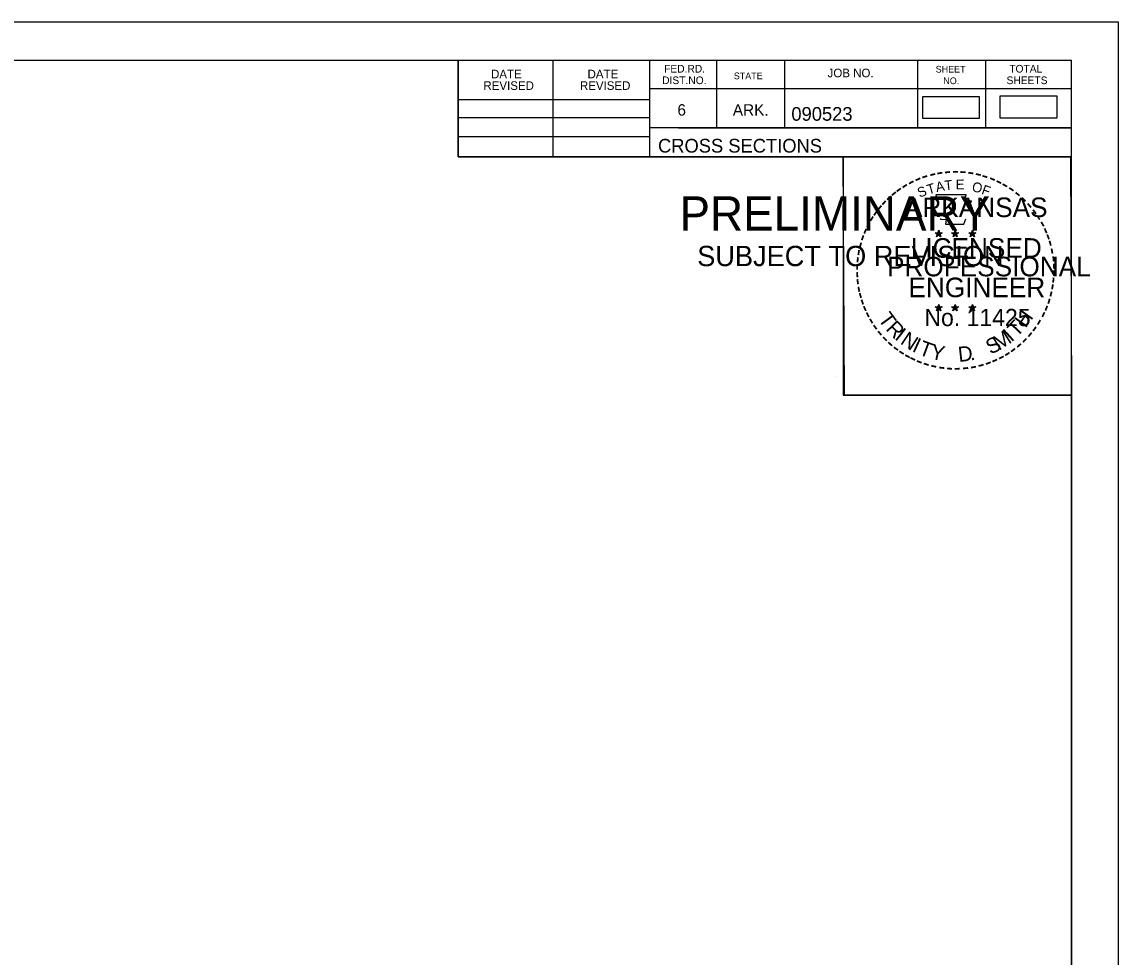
# Model space of a CAD drawing. Extents: x 1406028 to 1412453, y 321733 to 325986.
# Drawn here: x 1406640.9 to 1406752.8, y 324610.6 to 324706.1 of the extents above; entities that cross this region are included whole.
import ezdxf

# ---------------------------------------------------------------- set-up
doc = ezdxf.new("R2010")
doc.units = 0
for name, color, linetype in [('R_Border', 7, 'Continuous'), ('R_Border PE', 7, 'Continuous'), ('R_Border Prem', 7, 'Continuous'), ('R_Fin Surface', 7, 'Continuous'), ('R_No Plot', 7, 'Continuous')]:
    doc.layers.add(name, color=color, linetype=linetype)

msp = doc.modelspace()

# ---------------------------------------------------------------- linework, layer by layer
at = {"layer": 'R_Border'}
for p, q in [((1406431.89, 324702.17), (1406748.07, 324702.17)), ((1406685.43, 324692.29), (1406685.43, 324702.17)), ((1406695.11, 324692.29), (1406695.11, 324702.17)), ((1406704.97, 324702.17), (1406704.97, 324692.29)), ((1406711.81, 324702.17), (1406711.81, 324695.23)), ((1406718.75, 324702.17), (1406718.75, 324695.23)), ((1406732.33, 324702.17), (1406732.33, 324695.23)), ((1406739.27, 324702.17), (1406739.27, 324695.23)), ((1406748.07, 324496.71), (1406748.07, 324702.17)), ((1406748.07, 324699.23), (1406704.97, 324699.23)), ((1406748.07, 324699.25), (1406748.07, 324699.25)), ((1406685.43, 324698.15), (1406704.97, 324698.15)), ((1406685.43, 324696.29), (1406704.97, 324696.29)), ((1406748.07, 324695.23), (1406704.97, 324695.23)), ((1406707.93, 324695.23), (1406748.07, 324695.23)), ((1406685.43, 324694.35), (1406704.97, 324694.35)), ((1406748.07, 324692.29), (1406685.43, 324692.29))]:
    msp.add_line(p, q, dxfattribs=at)
at = {"layer": 'R_Border PE'}
for p, q in [((1406734.15, 324684.54), (1406734.5, 324684.43)), ((1406734.15, 324684.54), (1406734.41, 324684.5)), ((1406734.15, 324684.54), (1406734.39, 324684.42)), ((1406734.29, 324684.13), (1406734.5, 324684.43)), ((1406734.29, 324684.13), (1406734.41, 324684.38)), ((1406734.29, 324684.13), (1406734.5, 324684.35)), ((1406734.5, 324684.8), (1406734.46, 324684.54)), ((1406734.5, 324684.43), (1406734.5, 324684.8)), ((1406734.5, 324684.8), (1406734.55, 324684.55)), ((1406734.85, 324684.54), (1406734.5, 324684.43)), ((1406734.72, 324684.13), (1406734.5, 324684.43)), ((1406734.72, 324684.13), (1406734.5, 324684.35)), ((1406734.85, 324684.54), (1406734.56, 324684.49)), ((1406734.72, 324684.13), (1406734.58, 324684.43)), ((1406734.85, 324684.54), (1406734.65, 324684.44)), ((1406735.82, 324684.54), (1406736.17, 324684.43)), ((1406735.82, 324684.54), (1406736.08, 324684.5)), ((1406735.82, 324684.54), (1406736.06, 324684.42)), ((1406735.96, 324684.13), (1406736.17, 324684.43)), ((1406735.96, 324684.13), (1406736.08, 324684.38)), ((1406735.96, 324684.13), (1406736.17, 324684.35)), ((1406736.17, 324684.8), (1406736.13, 324684.54)), ((1406736.17, 324684.43), (1406736.17, 324684.8)), ((1406736.17, 324684.8), (1406736.22, 324684.55)), ((1406736.52, 324684.54), (1406736.17, 324684.43)), ((1406736.39, 324684.13), (1406736.17, 324684.43)), ((1406736.39, 324684.13), (1406736.17, 324684.35)), ((1406736.52, 324684.54), (1406736.23, 324684.49)), ((1406736.39, 324684.13), (1406736.25, 324684.43)), ((1406736.52, 324684.54), (1406736.32, 324684.44)), ((1406737.59, 324684.53), (1406737.94, 324684.42)), ((1406737.59, 324684.53), (1406737.84, 324684.49)), ((1406737.59, 324684.53), (1406737.83, 324684.41)), ((1406737.72, 324684.12), (1406737.94, 324684.42)), ((1406737.72, 324684.12), (1406737.85, 324684.37)), ((1406737.72, 324684.12), (1406737.94, 324684.34)), ((1406737.94, 324684.78), (1406737.9, 324684.53)), ((1406737.94, 324684.42), (1406737.94, 324684.78)), ((1406737.94, 324684.78), (1406737.99, 324684.53)), ((1406738.28, 324684.53), (1406737.94, 324684.42)), ((1406738.15, 324684.12), (1406737.94, 324684.42)), ((1406738.15, 324684.12), (1406737.94, 324684.34)), ((1406738.28, 324684.53), (1406738, 324684.48)), ((1406738.15, 324684.12), (1406738.01, 324684.41)), ((1406738.28, 324684.53), (1406738.08, 324684.43)), ((1406734.15, 324676.97), (1406734.5, 324676.86)), ((1406734.15, 324676.97), (1406734.4, 324676.92)), ((1406734.15, 324676.97), (1406734.39, 324676.85)), ((1406734.28, 324676.56), (1406734.5, 324676.86)), ((1406734.28, 324676.56), (1406734.41, 324676.81)), ((1406734.28, 324676.56), (1406734.5, 324676.78)), ((1406734.5, 324677.22), (1406734.46, 324676.97)), ((1406734.5, 324676.86), (1406734.5, 324677.22)), ((1406734.5, 324677.22), (1406734.55, 324676.97)), ((1406734.85, 324676.97), (1406734.5, 324676.86)), ((1406734.71, 324676.56), (1406734.5, 324676.86)), ((1406734.71, 324676.56), (1406734.5, 324676.78)), ((1406734.85, 324676.97), (1406734.56, 324676.92)), ((1406734.71, 324676.56), (1406734.58, 324676.85)), ((1406734.85, 324676.97), (1406734.64, 324676.87)), ((1406735.82, 324676.97), (1406736.17, 324676.86)), ((1406735.82, 324676.97), (1406736.07, 324676.92)), ((1406735.82, 324676.97), (1406736.06, 324676.85)), ((1406735.95, 324676.56), (1406736.17, 324676.86)), ((1406735.95, 324676.56), (1406736.08, 324676.81)), ((1406735.95, 324676.56), (1406736.17, 324676.78)), ((1406736.17, 324677.22), (1406736.13, 324676.97)), ((1406736.17, 324676.86), (1406736.17, 324677.22)), ((1406736.17, 324677.22), (1406736.22, 324676.97)), ((1406736.52, 324676.97), (1406736.17, 324676.86)), ((1406736.38, 324676.56), (1406736.17, 324676.86)), ((1406736.38, 324676.56), (1406736.17, 324676.78)), ((1406736.52, 324676.97), (1406736.23, 324676.92)), ((1406736.38, 324676.56), (1406736.24, 324676.85)), ((1406736.52, 324676.97), (1406736.31, 324676.87)), ((1406737.59, 324676.96), (1406737.94, 324676.85)), ((1406737.59, 324676.96), (1406737.84, 324676.91)), ((1406737.59, 324676.96), (1406737.82, 324676.84)), ((1406737.72, 324676.55), (1406737.94, 324676.85)), ((1406737.72, 324676.55), (1406737.85, 324676.8)), ((1406737.72, 324676.55), (1406737.93, 324676.77)), ((1406737.94, 324677.21), (1406737.89, 324676.96)), ((1406738.15, 324676.55), (1406737.93, 324676.77)), ((1406737.94, 324676.85), (1406737.94, 324677.21)), ((1406737.94, 324677.21), (1406737.98, 324676.96)), ((1406738.28, 324676.96), (1406737.94, 324676.85)), ((1406738.15, 324676.55), (1406737.94, 324676.85)), ((1406738.28, 324676.96), (1406738, 324676.91)), ((1406738.15, 324676.55), (1406738.01, 324676.84)), ((1406738.28, 324676.96), (1406738.08, 324676.86))]:
    msp.add_line(p, q, dxfattribs=at)
for points in [[(1406734.2, 324688.42), (1406734.46, 324687.59)], [(1406737.71, 324687.5), (1406737.85, 324687.78), (1406737.16, 324687.76), (1406737.31, 324688.42), (1406734.2, 324688.42)], [(1406734.69, 324686), (1406734.69, 324685.91), (1406735.25, 324685.89), (1406735.2, 324685.42), (1406737.07, 324685.42), (1406737.27, 324685.95)], [(1406734.5, 324684.8), (1406734.72, 324684.13), (1406734.15, 324684.54), (1406734.85, 324684.54), (1406734.29, 324684.13), (1406734.5, 324684.8)], [(1406736.17, 324684.8), (1406736.39, 324684.13), (1406735.82, 324684.54), (1406736.52, 324684.54), (1406735.96, 324684.13), (1406736.17, 324684.8)], [(1406737.94, 324684.78), (1406738.15, 324684.12), (1406737.59, 324684.53), (1406738.28, 324684.53), (1406737.72, 324684.12), (1406737.94, 324684.78)], [(1406734.5, 324677.22), (1406734.71, 324676.56), (1406734.15, 324676.97), (1406734.85, 324676.97), (1406734.28, 324676.56), (1406734.5, 324677.22)], [(1406736.17, 324677.22), (1406736.38, 324676.56), (1406735.82, 324676.97), (1406736.52, 324676.97), (1406735.95, 324676.56), (1406736.17, 324677.22)], [(1406737.94, 324677.21), (1406738.15, 324676.55), (1406737.59, 324676.96), (1406738.28, 324676.96), (1406737.72, 324676.55), (1406737.94, 324677.21)]]:
    msp.add_lwpolyline(points, dxfattribs=at)
for centre, radius in [((1406734.5, 324684.43), 0.172), ((1406734.5, 324684.43), 0.145), ((1406734.5, 324684.43), 0.116), ((1406734.5, 324684.43), 0.0991), ((1406734.5, 324684.43), 0.0747), ((1406734.5, 324684.43), 0.0495), ((1406734.5, 324684.43), 0.0296), ((1406736.17, 324684.43), 0.172), ((1406736.17, 324684.43), 0.145), ((1406736.17, 324684.43), 0.116), ((1406736.17, 324684.43), 0.0991), ((1406736.17, 324684.43), 0.0747), ((1406736.17, 324684.43), 0.0495), ((1406736.17, 324684.43), 0.0296), ((1406737.94, 324684.42), 0.172), ((1406737.94, 324684.42), 0.145), ((1406737.94, 324684.42), 0.116), ((1406737.94, 324684.42), 0.0991), ((1406737.94, 324684.42), 0.0747), ((1406737.94, 324684.42), 0.0495), ((1406737.94, 324684.42), 0.0296), ((1406734.5, 324676.86), 0.172), ((1406734.5, 324676.86), 0.145), ((1406734.5, 324676.86), 0.116), ((1406734.5, 324676.86), 0.0991), ((1406734.5, 324676.86), 0.0747), ((1406734.5, 324676.86), 0.0495), ((1406734.5, 324676.86), 0.0296), ((1406736.17, 324676.86), 0.172), ((1406736.17, 324676.86), 0.145), ((1406736.17, 324676.86), 0.116), ((1406736.17, 324676.86), 0.0991), ((1406736.17, 324676.86), 0.0747), ((1406736.17, 324676.86), 0.0495), ((1406736.17, 324676.86), 0.0296), ((1406737.93, 324676.85), 0.172), ((1406737.93, 324676.85), 0.145), ((1406737.93, 324676.85), 0.116), ((1406737.93, 324676.85), 0.0991), ((1406737.93, 324676.85), 0.0747), ((1406737.93, 324676.85), 0.0495), ((1406737.93, 324676.85), 0.0296)]:
    msp.add_circle(centre, radius, dxfattribs=at)
at = {"layer": 'R_Fin Surface'}
for points in [[(1406732.85, 324696.23), (1406738.68, 324696.23), (1406738.68, 324698.42), (1406732.85, 324698.42)], [(1406740.76, 324696.28), (1406746.59, 324696.28), (1406746.59, 324698.47), (1406740.76, 324698.47)]]:
    msp.add_lwpolyline(points, close=True, dxfattribs=at)
at = {"layer": 'R_No Plot'}
for p, q in [((1406419.49, 324706.06), (1406752.82, 324706.06)), ((1406724.1, 324669.83), (1406724.1, 324669.83))]:
    msp.add_line(p, q, dxfattribs=at)
for points in [[(1406419.48, 324706.06), (1406752.82, 324706.06), (1406752.82, 324492.72), (1406419.48, 324492.72)], [(1406665.81, 324702.17), (1406685.43, 324702.17), (1406685.43, 324692.29), (1406701.54, 324692.29), (1406724.74, 324692.29), (1406724.74, 324667.95), (1406748.07, 324667.95), (1406748.07, 324496.71), (1406431.89, 324496.71), (1406431.89, 324702.17)], [(1406724.74, 324692.29), (1406747.95, 324692.29), (1406748.07, 324667.95), (1406724.86, 324667.95)]]:
    msp.add_lwpolyline(points, close=True, dxfattribs=at)

# ---------------------------------------------------------------- texts
at = {"layer": 'R_Border'}
for s, height, p in [('DATE', 0.879, (1406688.77, 324700.3)), ('DATE', 0.879, (1406698.63, 324700.3)), ('FED.RD.', 0.782, (1406706.45, 324700.89)), ('STATE', 0.684, (1406713.57, 324700.21)), ('JOB NO.', 0.879, (1406723.15, 324700.41)), ('SHEET', 0.684, (1406734.19, 324700.89)), ('TOTAL', 0.782, (1406741.71, 324700.89)), ('REVISED', 0.879, (1406687.99, 324699.12)), ('REVISED', 0.879, (1406697.85, 324699.12)), ('DIST.NO.', 0.782, (1406706.25, 324699.71)), ('NO.', 0.684, (1406734.97, 324699.71)), ('SHEETS', 0.782, (1406741.43, 324699.71)), ('6', 1.17, (1406707.81, 324696.49)), ('ARK.', 1.172, (1406713.47, 324696.49)), ('090523', 1.4, (1406719.45, 324695.97)), ('CROSS SECTIONS', 1.4, (1406705.83, 324692.72))]:
    msp.add_text(s, height=height, rotation=360, dxfattribs=at).set_placement(p)
at = {"layer": 'R_Border PE'}
for s, height, rotation, p in [('-', 1.6, 10.2193, (1406734.37, 324689.95)), ('-', 1.6, 5.8968, (1406735.1, 324690.06)), ('-', 1.6, 0.1862, (1406735.87, 324690.13)), ('-', 1.6, 357.743, (1406736.6, 324690.12)), ('-', 1.6, 352.1617, (1406737.34, 324690.06)), ('-', 1.6, 28.7918, (1406731.68, 324688.96)), ('-', 1.6, 24.3072, (1406732.31, 324689.28)), ('-', 1.6, 19.1761, (1406732.94, 324689.55)), ('T', 1, 16.4036, (1406733.46, 324688.43)), ('-', 1.6, 13.6301, (1406733.69, 324689.79)), ('A', 1, 11.2132, (1406734.29, 324688.68)), ('T', 1, 6.0228, (1406735.14, 324688.85)), ('E', 1, 0.8323, (1406736.24, 324688.96)), ('O', 1, 350.4515, (1406737.85, 324688.75)), ('-', 1.6, 347.2049, (1406738.06, 324689.95)), ('-', 1.6, 342.3362, (1406738.69, 324689.79)), ('-', 1.6, 337.8551, (1406739.43, 324689.57)), ('-', 1.6, 334.1211, (1406740.06, 324689.3)), ('-', 1.6, 38.9507, (1406730.03, 324687.82)), ('-', 1.6, 36.2317, (1406730.5, 324688.2)), ('-', 1.6, 34.0636, (1406731.08, 324688.59)), ('S', 1, 21.594, (1406732.55, 324688.1)), ('F', 1, 340.0707, (1406738.8, 324688.52)), ('-', 1.6, 329.6409, (1406740.64, 324689.02)), ('-', 1.6, 325.8627, (1406741.28, 324688.66)), ('-', 1.6, 320.5297, (1406741.89, 324688.23)), ('-', 1.6, 50.6142, (1406728.74, 324686.44)), ('-', 1.6, 48.423, (1406729.14, 324686.92)), ('-', 1.6, 42.9622, (1406729.59, 324687.4)), ('ARKANSAS', 2, 360, (1406731.05, 324686.13)), ('-', 1.6, 315.5786, (1406742.49, 324687.74)), ('-', 1.6, 309.8797, (1406743.06, 324687.19)), ('-', 1.6, 58.0706, (1406728, 324685.34)), ('-', 1.6, 54.2325, (1406728.33, 324685.87)), ('-', 1.6, 306.6522, (1406743.58, 324686.59)), ('-', 1.4, 303.6753, (1406744.07, 324686.02)), ('-', 1.6, 62.8713, (1406727.69, 324684.73)), ('-', 1.6, 299.6684, (1406744.39, 324685.42)), ('-', 1.6, 72.3945, (1406727.21, 324683.49)), ('-', 1.6, 67.7743, (1406727.43, 324684.12)), ('LICENSED', 2, 360, (1406731.65, 324681.98)), ('DWB', 0.01, 360, (1406734.49, 324684.43)), ('DWB', 0.01, 360, (1406736.16, 324684.43)), ('DWB', 0.01, 360, (1406737.92, 324684.42)), ('-', 1.6, 294.6628, (1406744.71, 324684.8)), ('-', 1.6, 290.5728, (1406744.97, 324684.23)), ('-', 1.6, 75.461, (1406727.02, 324682.77)), ('-', 1.6, 285.1233, (1406745.2, 324683.65)), ('-', 1.6, 280.5493, (1406745.4, 324682.9)), ('-', 1.6, 85.1863, (1406726.81, 324681.37)), ('-', 1.6, 81.2013, (1406726.88, 324682.06)), ('PROFESSIONAL', 2, 360, (1406729.22, 324680.08)), ('-', 1.6, 276.5962, (1406745.57, 324682.14)), ('-', 1.6, 89.0622, (1406726.78, 324680.67)), ('-', 1.6, 274.3301, (1406745.63, 324681.41)), ('-', 1.6, 269.9407, (1406745.66, 324680.78)), ('-', 1.6, 94.1959, (1406726.82, 324679.94)), ('-', 1.6, 98.9479, (1406726.89, 324679.28)), ('ENGINEER', 2, 360, (1406731.41, 324677.95)), ('-', 1.6, 263.5172, (1406745.64, 324680.12)), ('-', 1.6, 101.7149, (1406727.02, 324678.54)), ('-', 1.6, 105.4578, (1406727.19, 324677.95)), ('-', 1.6, 255.7626, (1406745.46, 324678.78)), ('-', 1.6, 260.9953, (1406745.57, 324679.46)), ('-', 1.6, 109.0874, (1406727.4, 324677.32)), ('-', 1.6, 252.8681, (1406745.28, 324678.06)), ('-', 1.6, 114.0643, (1406727.66, 324676.72)), ('-', 1.6, 115.7289, (1406727.96, 324676.1)), ('T', 1.54, 306.0406, (1406728.26, 324675.7)), ('No. 11425', 1.757, 360, (1406733.04, 324675)), ('DWB', 0.01, 360, (1406734.49, 324676.85)), ('DWB', 0.01, 360, (1406736.16, 324676.85)), ('DWB', 0.01, 360, (1406737.92, 324676.84)), ('H', 1.54, 54.6088, (1406743.38, 324674.73)), ('-', 1.6, 244.6197, (1406744.79, 324676.76)), ('-', 1.6, 247.8887, (1406745.06, 324677.39)), ('-', 1.6, 120.4471, (1406728.32, 324675.52)), ('-', 1.6, 125.8934, (1406728.72, 324674.96)), ('R', 1.54, 314.005, (1406729.02, 324674.65)), ('T', 1.54, 46.6444, (1406742.49, 324673.79)), ('-', 1.6, 239.0712, (1406744.4, 324676.01)), ('-', 1.6, 130.7181, (1406729.18, 324674.41)), ('-', 1.6, 134.2238, (1406729.7, 324673.86)), ('I', 1.54, 321.9694, (1406729.92, 324673.72)), ('N', 1.54, 326.5002, (1406730.49, 324673.25)), ('M', 1.54, 32.6563, (1406740.64, 324672.46)), ('I', 1.54, 42.1136, (1406741.93, 324673.31)), ('-', 1.6, 231.2538, (1406743.57, 324674.79)), ('-', 1.6, 233.8452, (1406744, 324675.36)), ('-', 1.6, 138.9338, (1406730.22, 324673.4)), ('-', 1.6, 144.6463, (1406730.78, 324672.99)), ('I', 1.54, 335.3603, (1406731.7, 324672.46)), ('T', 1.54, 339.8912, (1406732.36, 324672.13)), ('Y', 1.54, 347.8556, (1406733.58, 324671.69)), ('D', 1.54, 6.3969, (1406736.56, 324671.33)), ('S', 1.54, 26.9312, (1406739.8, 324672.06)), ('-', 1.6, 221.0851, (1406742.57, 324673.72)), ('-', 1.6, 225.7653, (1406743.09, 324674.23)), ('-', 1.6, 148.0898, (1406731.34, 324672.62)), ('-', 1.6, 151.5704, (1406731.92, 324672.29)), ('-', 1.6, 154.6002, (1406732.44, 324672.05)), ('.', 1.54, 13.7642, (1406737.75, 324671.46)), ('-', 1.6, 204.2516, (1406740.3, 324672.19)), ('-', 1.6, 207.3568, (1406740.93, 324672.51)), ('-', 1.6, 212.2491, (1406741.48, 324672.86)), ('-', 1.6, 215.7363, (1406742.02, 324673.25)), ('-', 1.6, 158.5612, (1406733.07, 324671.79)), ('-', 1.6, 162.7983, (1406733.75, 324671.58)), ('-', 1.6, 167.5555, (1406734.47, 324671.42)), ('-', 1.6, 173.1155, (1406735.24, 324671.31)), ('-', 1.6, 176.5183, (1406735.99, 324671.25)), ('-', 1.6, 181.5918, (1406736.73, 324671.27)), ('-', 1.6, 185.8167, (1406737.54, 324671.35)), ('-', 1.6, 191.2858, (1406738.28, 324671.48)), ('-', 1.6, 195.4743, (1406739.01, 324671.68)), ('-', 1.6, 200.7184, (1406739.68, 324671.92))]:
    msp.add_text(s, height=height, rotation=rotation, dxfattribs=at).set_placement(p)
at = {"layer": 'R_Border Prem'}
for s, height, p in [('PRELIMINARY', 3.5, (1406708.02, 324684.75)), ('DWB', 0.01, (1406708.77, 324686.6)), ('SUBJECT TO REVISION', 2.0751, (1406709.83, 324681.12))]:
    msp.add_text(s, height=height, rotation=360, dxfattribs=at).set_placement(p)

doc.saveas('drawing.dxf')
